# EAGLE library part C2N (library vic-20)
Datassette connector
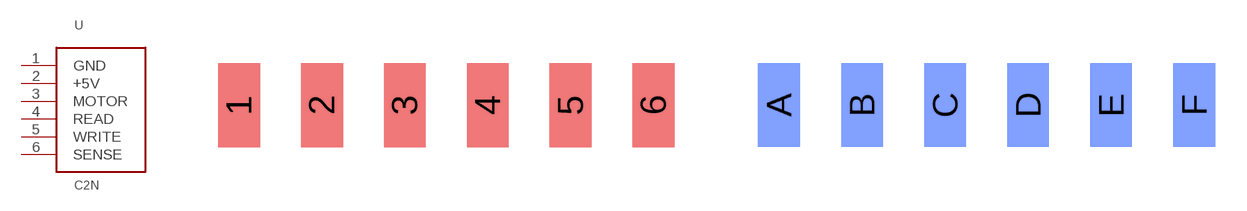
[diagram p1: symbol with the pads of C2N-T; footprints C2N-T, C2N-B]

Designator prefix -

## C2N-T  [C2N-T]
1  GND  pas
2  +5V  pas
3  MOTOR  out
4  READ  in
5  WRITE  in
6  SENSE  in

## C2N-B  [C2N-B]
A  GND  pas
B  +5V  pas
C  MOTOR  out
D  READ  in
E  WRITE  in
F  SENSE  in

## Footprint C2N-T (pad centres in mm)
Top-side pads for the C2N
smd 1.98 x 3.96: 1 -9.8,0; 2 -5.88,0; 3 -1.96,0; 4 1.96,0; 5 5.88,0; 6 9.8,0

## Footprint C2N-B (pad centres in mm)
Bottom-side pads for the C2N
smd 1.98 x 3.96 bottom: A -9.9,0; B -5.94,0; C -1.98,0; D 1.98,0; E 5.94,0; F 9.9,0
